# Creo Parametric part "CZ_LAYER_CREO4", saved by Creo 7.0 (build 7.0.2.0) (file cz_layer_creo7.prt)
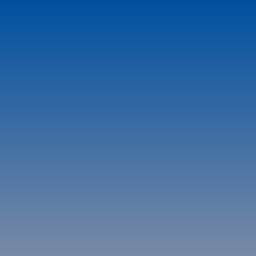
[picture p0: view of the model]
Units: Custom; MM, KILOGRAM, SECS

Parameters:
  BEARBEITER = "."
  ERSTELLUNGSDATUM = "."
  KONSTRUKTIONSGRUPPE = "."
  ZEICHNUNGSNUMMER = "000000-0000-000/01"
  TEILDOKUMENT = "001"
  VERSION = "01"
  MATERIALNUMMER = "000000-0000-000"
  KOMP_STUFE = "T"
  KOMP_CHAR = "M"
  BENENNUNG = "XXXXX"

Other parameters: PREIS

Layers: ACHSEN, BOHRUNGSNOTIZEN, EBENEN, FLAECHEN, FL_SCHWEISS, GEWINDE, KOORDSYS, KOSMETIK, KURVEN, MERGE, PUNKTE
